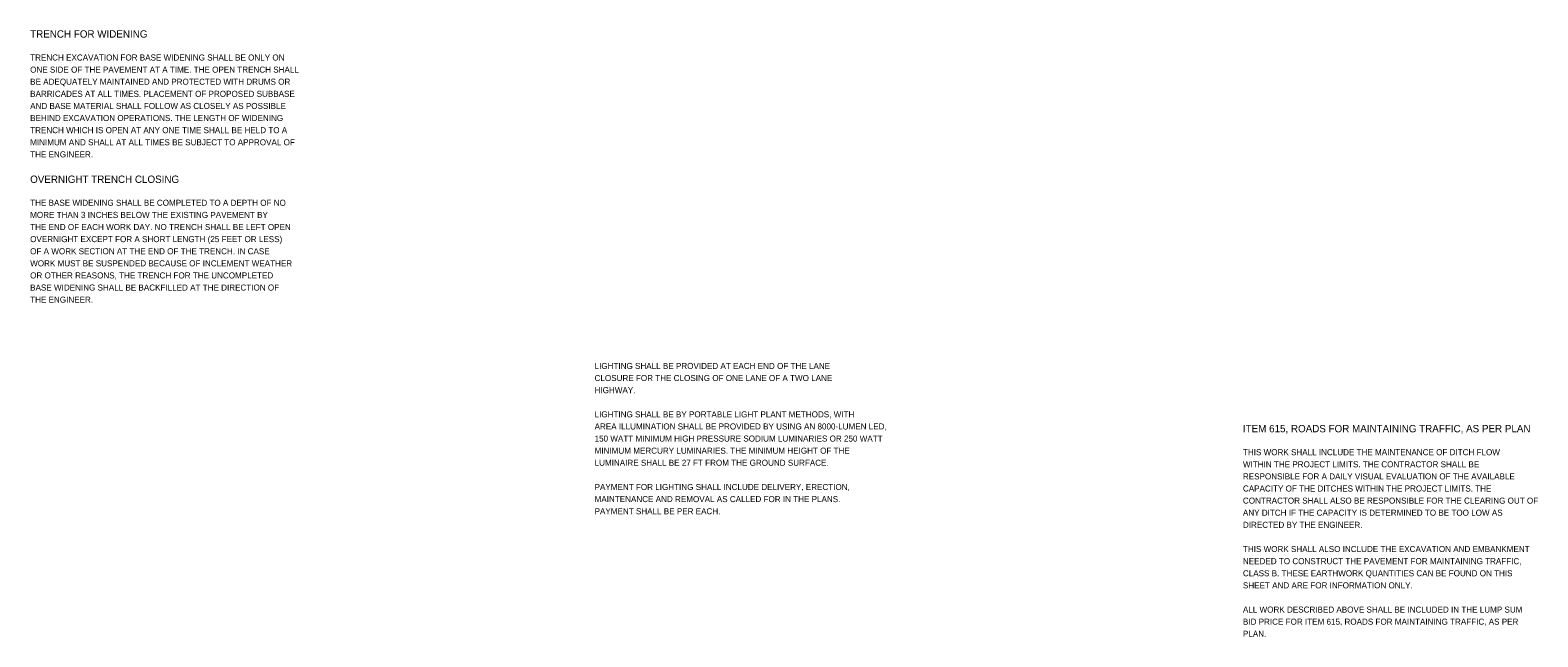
# Model space of a CAD drawing. Extents: x -18.3 to 50.3, y -3.1 to 38.9.
# Drawn here: x -18.25 to 16.65, y 24.9 to 38.93 of the extents above; entities that cross this region are included whole.
import ezdxf

# ---------------------------------------------------------------- set-up
doc = ezdxf.new("R2010")
doc.units = 0
doc.layers.add('SH_Text', color=7, linetype='Continuous')

msp = doc.modelspace()

# ---------------------------------------------------------------- texts
at = {"layer": 'SH_Text'}
for s, height, p in [('TRENCH FOR WIDENING', 0.17, (-18.254, 38.759)), ('TRENCH EXCAVATION FOR BASE WIDENING SHALL BE ONLY ON', 0.14, (-18.254, 38.229)), ('ONE SIDE OF THE PAVEMENT AT A TIME. THE OPEN TRENCH SHALL', 0.14, (-18.254, 37.949)), ('BE ADEQUATELY MAINTAINED AND PROTECTED WITH DRUMS OR', 0.14, (-18.254, 37.669)), ('BARRICADES AT ALL TIMES. PLACEMENT OF PROPOSED SUBBASE', 0.14, (-18.254, 37.389)), ('AND BASE MATERIAL SHALL FOLLOW AS CLOSELY AS POSSIBLE', 0.14, (-18.254, 37.109)), ('TRENCH WHICH IS OPEN AT ANY ONE TIME SHALL BE HELD TO A', 0.14, (-18.254, 36.549)), ('BEHIND EXCAVATION OPERATIONS. THE LENGTH OF WIDENING', 0.14, (-18.254, 36.829)), ('MINIMUM AND SHALL AT ALL TIMES BE SUBJECT TO APPROVAL OF', 0.14, (-18.254, 36.269)), ('THE ENGINEER.', 0.14, (-18.254, 35.989)), ('OVERNIGHT TRENCH CLOSING', 0.17, (-18.254, 35.399)), ('THE BASE WIDENING SHALL BE COMPLETED TO A DEPTH OF NO', 0.14, (-18.254, 34.869)), ('MORE THAN 3 INCHES BELOW THE EXISTING PAVEMENT BY', 0.14, (-18.254, 34.589)), ('THE END OF EACH WORK DAY. NO TRENCH SHALL BE LEFT OPEN', 0.14, (-18.254, 34.309)), ('OVERNIGHT EXCEPT FOR A SHORT LENGTH (25 FEET OR LESS)', 0.14, (-18.254, 34.029)), ('OF A WORK SECTION AT THE END OF THE TRENCH. IN CASE', 0.14, (-18.254, 33.749)), ('WORK MUST BE SUSPENDED BECAUSE OF INCLEMENT WEATHER', 0.14, (-18.254, 33.469)), ('OR OTHER REASONS, THE TRENCH FOR THE UNCOMPLETED', 0.14, (-18.254, 33.189)), ('BASE WIDENING SHALL BE BACKFILLED AT THE DIRECTION OF', 0.14, (-18.254, 32.909)), ('THE ENGINEER.', 0.14, (-18.254, 32.629)), ('LIGHTING SHALL BE PROVIDED AT EACH END OF THE LANE', 0.14, (-5.188, 31.096)), ('CLOSURE FOR THE CLOSING OF ONE LANE OF A TWO LANE', 0.14, (-5.188, 30.816)), ('HIGHWAY.', 0.14, (-5.188, 30.536)), ('LIGHTING SHALL BE BY PORTABLE LIGHT PLANT METHODS, WITH', 0.14, (-5.188, 29.976)), ('AREA ILLUMINATION SHALL BE PROVIDED BY USING AN 8000-LUMEN LED,', 0.14, (-5.188, 29.696)), ('ITEM 615, ROADS FOR MAINTAINING TRAFFIC, AS PER PLAN', 0.17, (9.82, 29.631)), ('150 WATT MINIMUM HIGH PRESSURE SODIUM LUMINARIES OR 250 WATT', 0.14, (-5.188, 29.416)), ('MINIMUM MERCURY LUMINARIES. THE MINIMUM HEIGHT OF THE', 0.14, (-5.188, 29.136)), ('LUMINAIRE SHALL BE 27 FT FROM THE GROUND SURFACE.', 0.14, (-5.188, 28.856)), ('THIS WORK SHALL INCLUDE THE MAINTENANCE OF DITCH FLOW ', 0.14, (9.82, 29.101)), ('WITHIN THE PROJECT LIMITS. THE CONTRACTOR SHALL BE ', 0.14, (9.82, 28.821)), ('RESPONSIBLE FOR A DAILY VISUAL EVALUATION OF THE AVAILABLE ', 0.14, (9.82, 28.541)), ('PAYMENT FOR LIGHTING SHALL INCLUDE DELIVERY, ERECTION,', 0.14, (-5.188, 28.296)), ('CAPACITY OF THE DITCHES WITHIN THE PROJECT LIMITS. THE ', 0.14, (9.82, 28.261)), ('MAINTENANCE AND REMOVAL AS CALLED FOR IN THE PLANS.', 0.14, (-5.188, 28.016)), ('CONTRACTOR SHALL ALSO BE RESPONSIBLE FOR THE CLEARING OUT OF ', 0.14, (9.82, 27.981)), ('PAYMENT SHALL BE PER EACH.', 0.14, (-5.188, 27.736)), ('ANY DITCH IF THE CAPACITY IS DETERMINED TO BE TOO LOW AS ', 0.14, (9.82, 27.701)), ('DIRECTED BY THE ENGINEER. ', 0.14, (9.82, 27.421)), ('THIS WORK SHALL ALSO INCLUDE THE EXCAVATION AND EMBANKMENT ', 0.14, (9.82, 26.861)), ('NEEDED TO CONSTRUCT THE PAVEMENT FOR MAINTAINING TRAFFIC, ', 0.14, (9.82, 26.581)), ('CLASS B. THESE EARTHWORK QUANTITIES CAN BE FOUND ON THIS ', 0.14, (9.82, 26.301)), ('SHEET AND ARE FOR INFORMATION ONLY. ', 0.14, (9.82, 26.021)), ('ALL WORK DESCRIBED ABOVE SHALL BE INCLUDED IN THE LUMP SUM ', 0.14, (9.82, 25.461)), ('BID PRICE FOR ITEM 615, ROADS FOR MAINTAINING TRAFFIC, AS PER ', 0.14, (9.82, 25.181)), ('PLAN. ', 0.14, (9.82, 24.901))]:
    msp.add_text(s, height=height, dxfattribs=at).set_placement(p)

doc.saveas('drawing.dxf')
